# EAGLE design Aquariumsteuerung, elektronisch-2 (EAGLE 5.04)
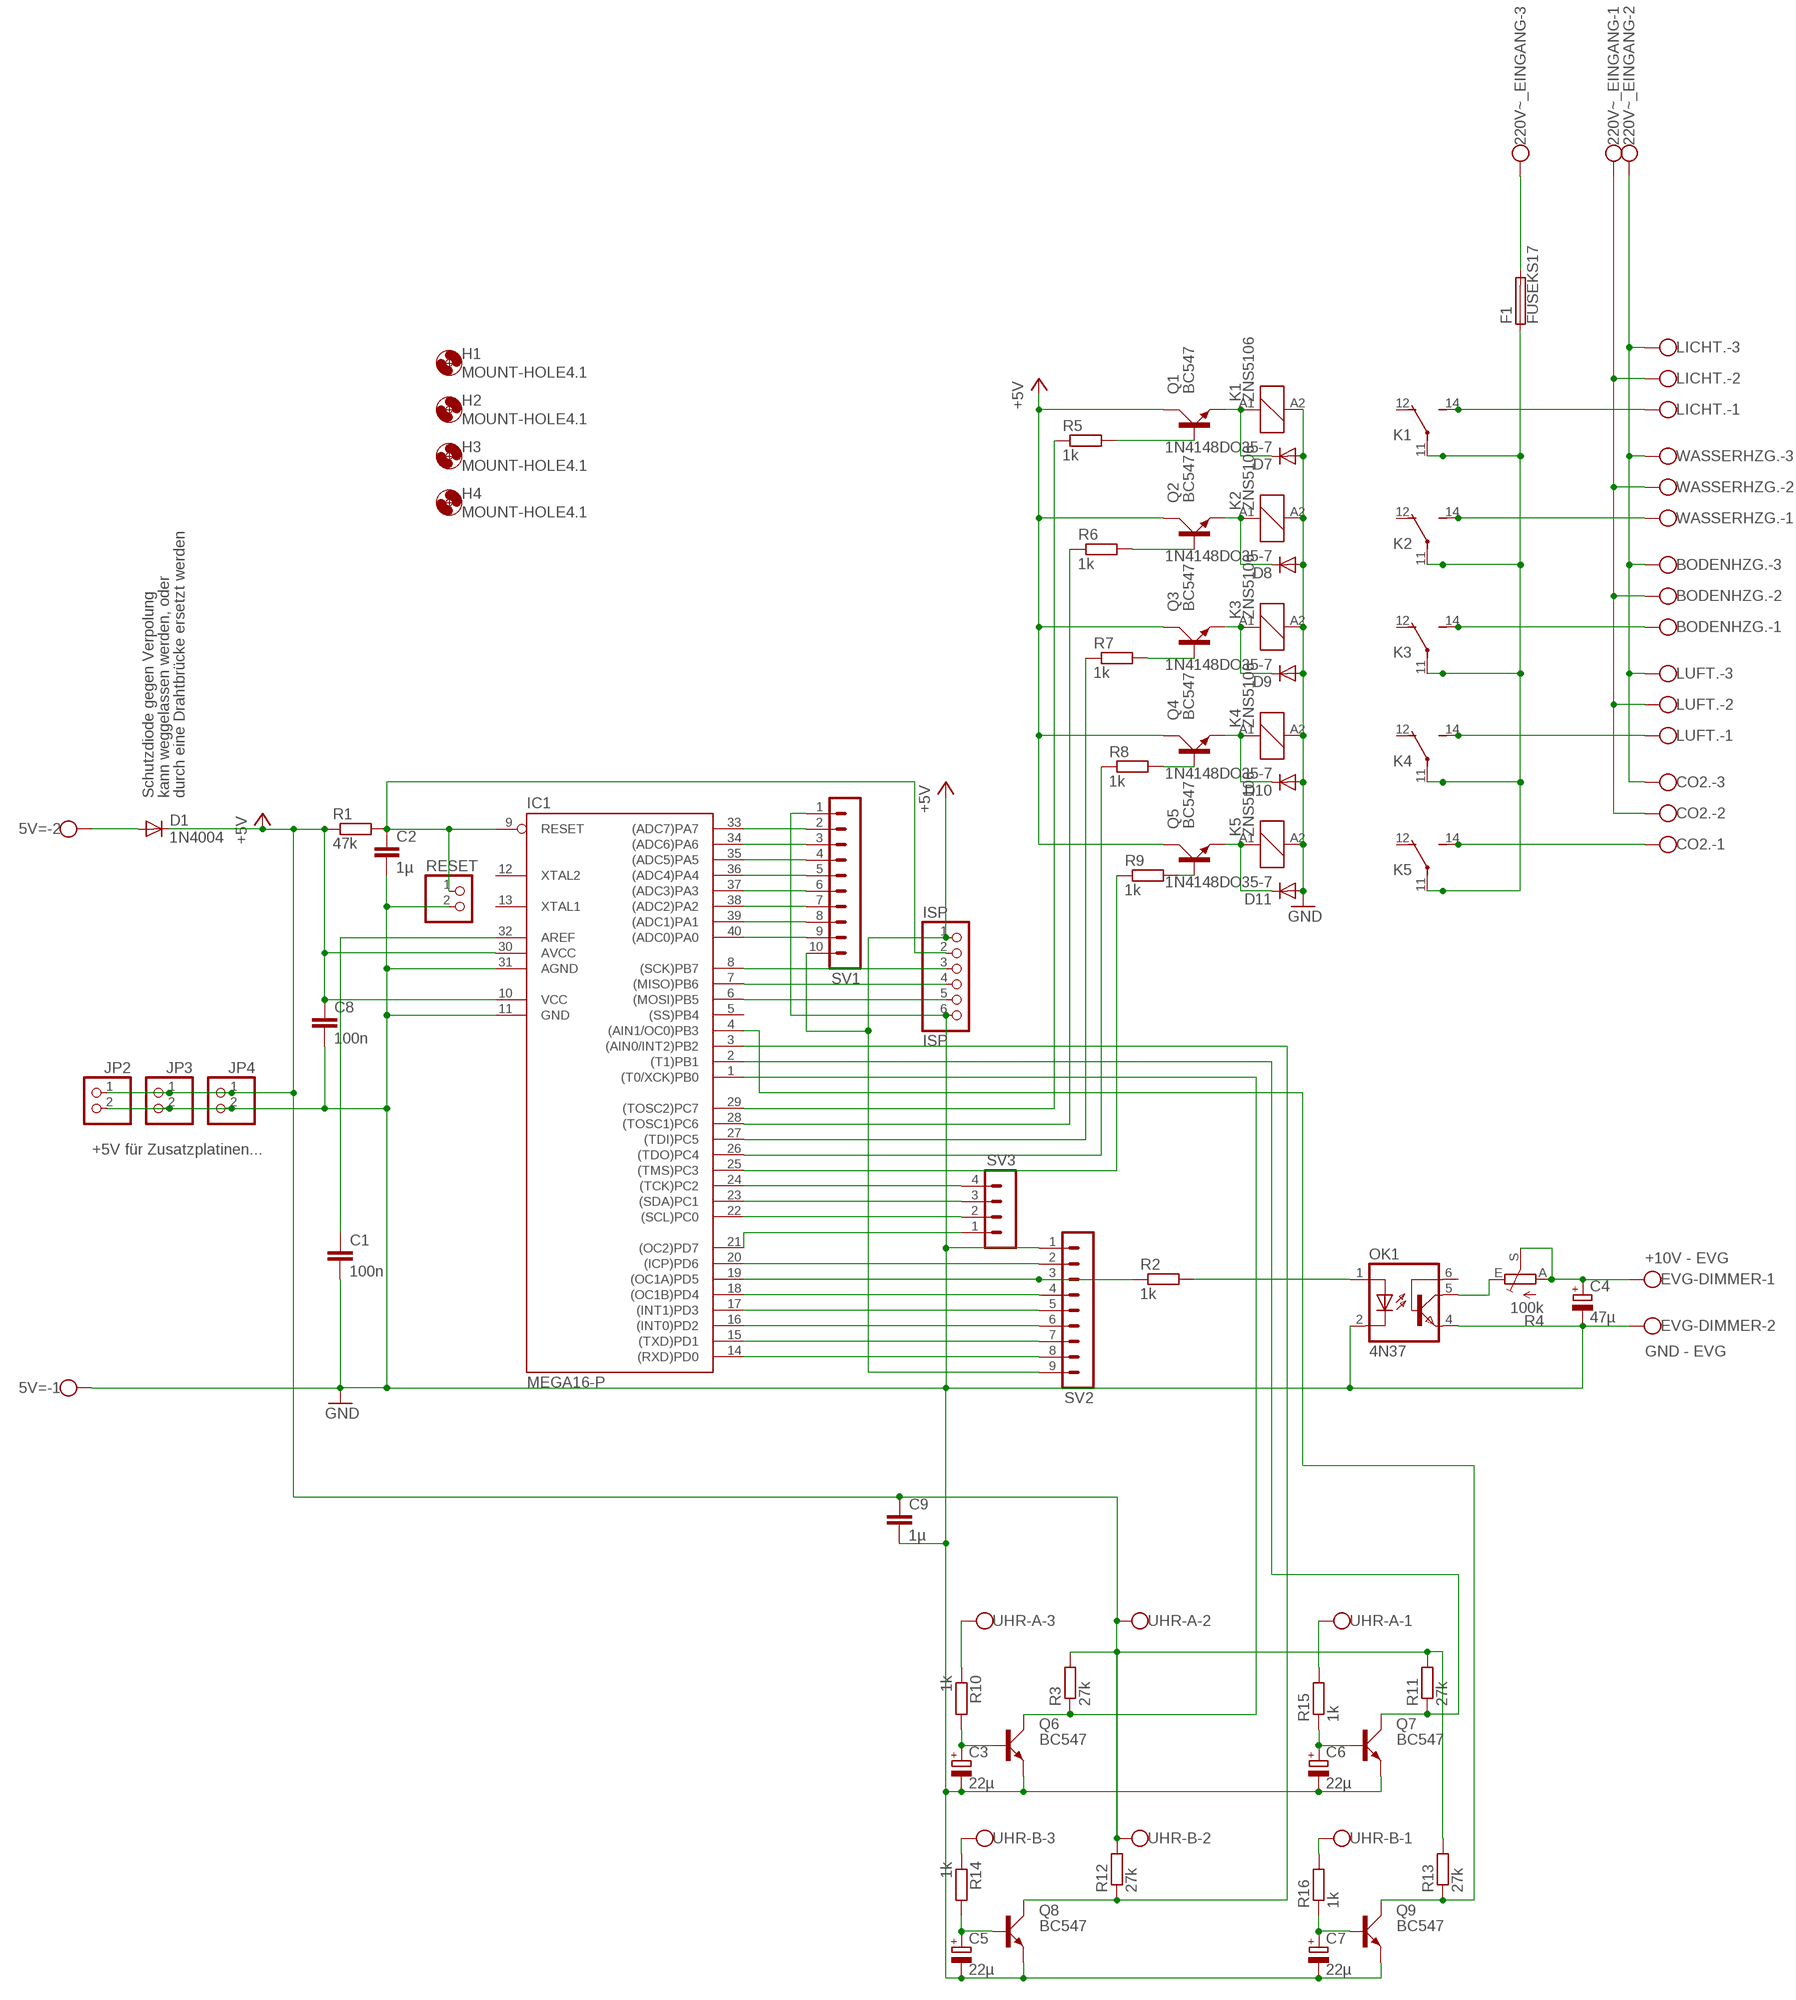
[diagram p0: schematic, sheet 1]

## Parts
5V=  W237-02P  [W237-132]
220V~_EINGANG  W237-03P  [W237-133]
BODENHZG.  W237-03P  [W237-133]
C1  100n  C-EU050-025X075  [C050-025X075]
C2  1µ  C-EU050-025X075  [C050-025X075]
C3  22µ  CPOL-EUE2.5-6  [E2,5-6]
C4  47µ  CPOL-EUE2.5-5  [E2,5-5]
C5  22µ  CPOL-EUE2.5-6  [E2,5-6]
C6  22µ  CPOL-EUE2.5-6  [E2,5-6]
C7  22µ  CPOL-EUE2.5-6  [E2,5-6]
C8  100n  C-EU050-025X075  [C050-025X075]
C9  1µ  C-EU050-025X075  [C050-025X075]
CO2.  W237-03P  [W237-133]
D1  1N4004  [DO41-10]
D7  1N4148DO35-7  [DO35-7]
D8  1N4148DO35-7  [DO35-7]
D9  1N4148DO35-7  [DO35-7]
D10  1N4148DO35-7  [DO35-7]
D11  1N4148DO35-7  [DO35-7]
EVG-DIMMER  W237-02P  [W237-132]
F1  FUSEKS17  [KS17]
H1  MOUNT-HOLE4.1  [4,1]
H2  MOUNT-HOLE4.1  [4,1]
H3  MOUNT-HOLE4.1  [4,1]
H4  MOUNT-HOLE4.1  [4,1]
IC1  MEGA16-P  [DIL40]
ISP  ISP  PINHD-1X6  [1X06]
JP2  PINHD-1X2  [1X02]
JP3  PINHD-1X2  [1X02]
JP4  PINHD-1X2  [1X02]
K1  ZNS5106  [ZN5]
K2  ZNS5106  [ZN5]
K3  ZNS5106  [ZN5]
K4  ZNS5106  [ZN5]
K5  ZNS5106  [ZN5]
LICHT.  W237-03P  [W237-133]
LUFT.  W237-03P  [W237-133]
OK1  4N37  [DIL06]
Q1  BC547  [SOT54A]
Q2  BC547  [SOT54A]
Q3  BC547  [SOT54A]
Q4  BC547  [SOT54A]
Q5  BC547  [SOT54A]
Q6  BC547  [SOT54A]
Q7  BC547  [SOT54A]
Q8  BC547  [SOT54A]
Q9  BC547  [SOT54A]
R1  47k  R-EU_0207/10  [0207/10]
R2  1k  R-EU_0207/10  [0207/10]
R3  27k  R-EU_0207/10  [0207/10]
R4  100k  TRIM_EU-S64W  [S64W]
R5  1k  R-EU_0207/10  [0207/10]
R6  1k  R-EU_0207/10  [0207/10]
R7  1k  R-EU_0207/10  [0207/10]
R8  1k  R-EU_0207/10  [0207/10]
R9  1k  R-EU_0207/10  [0207/10]
R10  1k  R-EU_0207/10  [0207/10]
R11  27k  R-EU_0207/10  [0207/10]
R12  27k  R-EU_0207/10  [0207/10]
R13  27k  R-EU_0207/10  [0207/10]
R14  1k  R-EU_0207/10  [0207/10]
R15  1k  R-EU_0207/10  [0207/10]
R16  1k  R-EU_0207/10  [0207/10]
RESET  PINHD-1X2  [1X02]
SV1  MA10-1  [MA10-1]
SV2  MA09-1  [MA09-1]
SV3  MA04-1  [MA04-1]
UHR-A  W237-03P  [W237-133]
UHR-B  W237-03P  [W237-133]
WASSERHZG.  W237-03P  [W237-133]

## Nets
+5V: C8.1 C9.1 D1.C IC1.10(VCC) IC1.30(AVCC) ISP.1 JP2.1 JP3.1 JP4.1 Q1.C Q2.C Q3.C Q4.C Q5.C R1.1 R3.2 R11.2 R12.2 R13.2 SV1.10 SV2.9 UHR-A.2 UHR-B.2
GND: 5V=.1 C1.2 C2.2 C3.- C4.- C5.- C6.- C7.- C8.2 C9.2 D7.A D8.A D9.A D10.A D11.A EVG-DIMMER.2 IC1.11(GND) IC1.31(AGND) ISP.6 JP2.2 JP3.2 JP4.2 K1.A2 K2.A2 K3.A2 K4.A2 K5.A2 OK1.2(C) OK1.4(EMI) Q6.E Q7.E Q8.E Q9.E RESET.2 SV1.1 SV2.1
L: F1.1 K1.11(2:P) K2.11(2:P) K3.11(2:P) K4.11(2:P) K5.11(2:P)
N: 220V~_EINGANG.1 BODENHZG..2 CO2..2 LICHT..2 LUFT..2 WASSERHZG..2
N$1: C3.+ Q6.B R10.2
N$2: C1.1 IC1.32(AREF)
N$3: IC1.19((OC1A)PD5) R2.1 SV2.3
N$4: K1.14(2:S) LICHT..1
N$5: K2.14(2:S) WASSERHZG..1
N$6: BODENHZG..1 K3.14(2:S)
N$7: K4.14(2:S) LUFT..1
N$8: CO2..1 K5.14(2:S)
N$9: D7.C K1.A1 Q1.E
N$10: D8.C K2.A1 Q2.E
N$11: 5V=.2 D1.A
N$12: IC1.8((SCK)PB7) ISP.3
N$13: D9.C K3.A1 Q3.E
N$14: D10.C K4.A1 Q4.E
N$15: OK1.1(A) R2.2
N$16: OK1.5(COL) R4.E
N$17: D11.C K5.A1 Q5.E
N$18: C4.+ EVG-DIMMER.1 R4.A R4.S
N$19: IC1.29((TOSC2)PC7) R5.1
N$20: IC1.28((TOSC1)PC6) R6.1
N$21: IC1.27((TDI)PC5) R7.1
N$22: IC1.26((TDO)PC4) R8.1
N$23: IC1.25((TMS)PC3) R9.1
N$24: IC1.7((MISO)PB6) ISP.4
N$25: IC1.6((MOSI)PB5) ISP.5
N$26: C2.1 IC1.9(RESET) ISP.2 R1.2 RESET.1
N$27: IC1.40((ADC0)PA0) SV1.9
N$28: IC1.39((ADC1)PA1) SV1.8
N$29: IC1.38((ADC2)PA2) SV1.7
N$30: IC1.24((TCK)PC2) SV3.4
N$31: IC1.23((SDA)PC1) SV3.3
N$32: IC1.22((SCL)PC0) SV3.2
N$33: IC1.37((ADC3)PA3) SV1.6
N$34: C7.+ Q9.B R16.1
N$35: IC1.2((T1)PB1) Q7.C R11.1
N$36: IC1.3((AIN0/INT2)PB2) Q8.C R12.1
N$37: IC1.4((AIN1/OC0)PB3) Q9.C R13.1
N$38: IC1.36((ADC4)PA4) SV1.5
N$39: R10.1 UHR-A.3
N$40: IC1.35((ADC5)PA5) SV1.4
N$41: IC1.34((ADC6)PA6) SV1.3
N$42: IC1.33((ADC7)PA7) SV1.2
N$43: IC1.1((T0/XCK)PB0) Q6.C R3.1
N$44: R14.1 UHR-B.3
N$45: C6.+ Q7.B R15.1
N$46: IC1.14((RXD)PD0) SV2.8
N$47: IC1.15((TXD)PD1) SV2.7
N$48: IC1.16((INT0)PD2) SV2.6
N$49: IC1.17((INT1)PD3) SV2.5
N$50: IC1.18((OC1B)PD4) SV2.4
N$51: IC1.20((ICP)PD6) SV2.2
N$52: IC1.21((OC2)PD7) SV3.1
N$53: C5.+ Q8.B R14.2
N$54: R16.2 UHR-B.1
N$55: R15.2 UHR-A.1
N$56: 220V~_EINGANG.3 F1.2
N$59: Q1.B R5.2
N$60: Q2.B R6.2
N$61: Q3.B R7.2
N$62: Q4.B R8.2
N$63: Q5.B R9.2
PE: 220V~_EINGANG.2 BODENHZG..3 CO2..3 LICHT..3 LUFT..3 WASSERHZG..3
Unconnected: IC1.5((SS)PB4) IC1.12(XTAL2) IC1.13(XTAL1) K1.12(2:O) K2.12(2:O) K3.12(2:O) K4.12(2:O) K5.12(2:O) OK1.6(BAS)

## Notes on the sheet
- Schutzdiode gegen Verpolung | kann weggelassen werden, oder | durch eine Drahtbrücke ersetzt werden
- +5V für Zusatzplatinen...
- +10V - EVG
- GND - EVG

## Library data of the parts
5V= EVG-DIMMER = Verbinder von Wago, Raster 5.08:W237-02P: WAGO SREW CLAMP
220V~_EINGANG BODENHZG. CO2. LICHT. LUFT. UHR-A UHR-B WASSERHZG. = Verbinder von Wago, Raster 5.08:W237-03P: WAGO SREW CLAMP
C1 C2 C8 C9 = Widerstände & Kondensatoren:C-EU: CAPACITOR, European symbol
C3-C7 = Widerstände & Kondensatoren:CPOL-EU: POLARIZED CAPACITOR, European symbol
D1 = Dioden:1N4004: DIODE
D7-D11 = diode:1N4148: DIODE
F1 = fuse:FUSE: Fuse
H1-H4 = Montagelöcher:MOUNT-HOLE: MOUNTING HOLE with drill center marker
IC1 = avr-4:MEGA16-P: MICROCONTROLLER 16 Kbytes FLASH 1 kbytes SRAM 512 bytes EEPROM USART 8-channel 10 bit ADC
ISP = Steckerleisten:PINHD-1X6: PIN HEADER
JP2-JP4 RESET = Steckerleisten:PINHD-1X2: PIN HEADER
K1-K5 = relay:ZNS5*: Miniature Power PCB Relay SCHRACK 1pole 10 A Source: http://www.schrack.com/.. 5847.pdf
OK1 = Optokoppler:4N37: MOTOROLA OPTO COUPLER
Q1-Q9 = Transistor-Kleinsignal:BC547: NPN TRANSISTOR
R1-R3 R5-R16 = Widerstände & Kondensatoren:R-EU_: RESISTOR, European symbol
R4 = Poti's:TRIM_EU-: POTENTIOMETER
SV1 = Steckerleisten, männlich:MA10-1: PIN HEADER
SV2 = Steckerleisten, männlich:MA09-1: PIN HEADER
SV3 = Steckerleisten, männlich:MA04-1: PIN HEADER

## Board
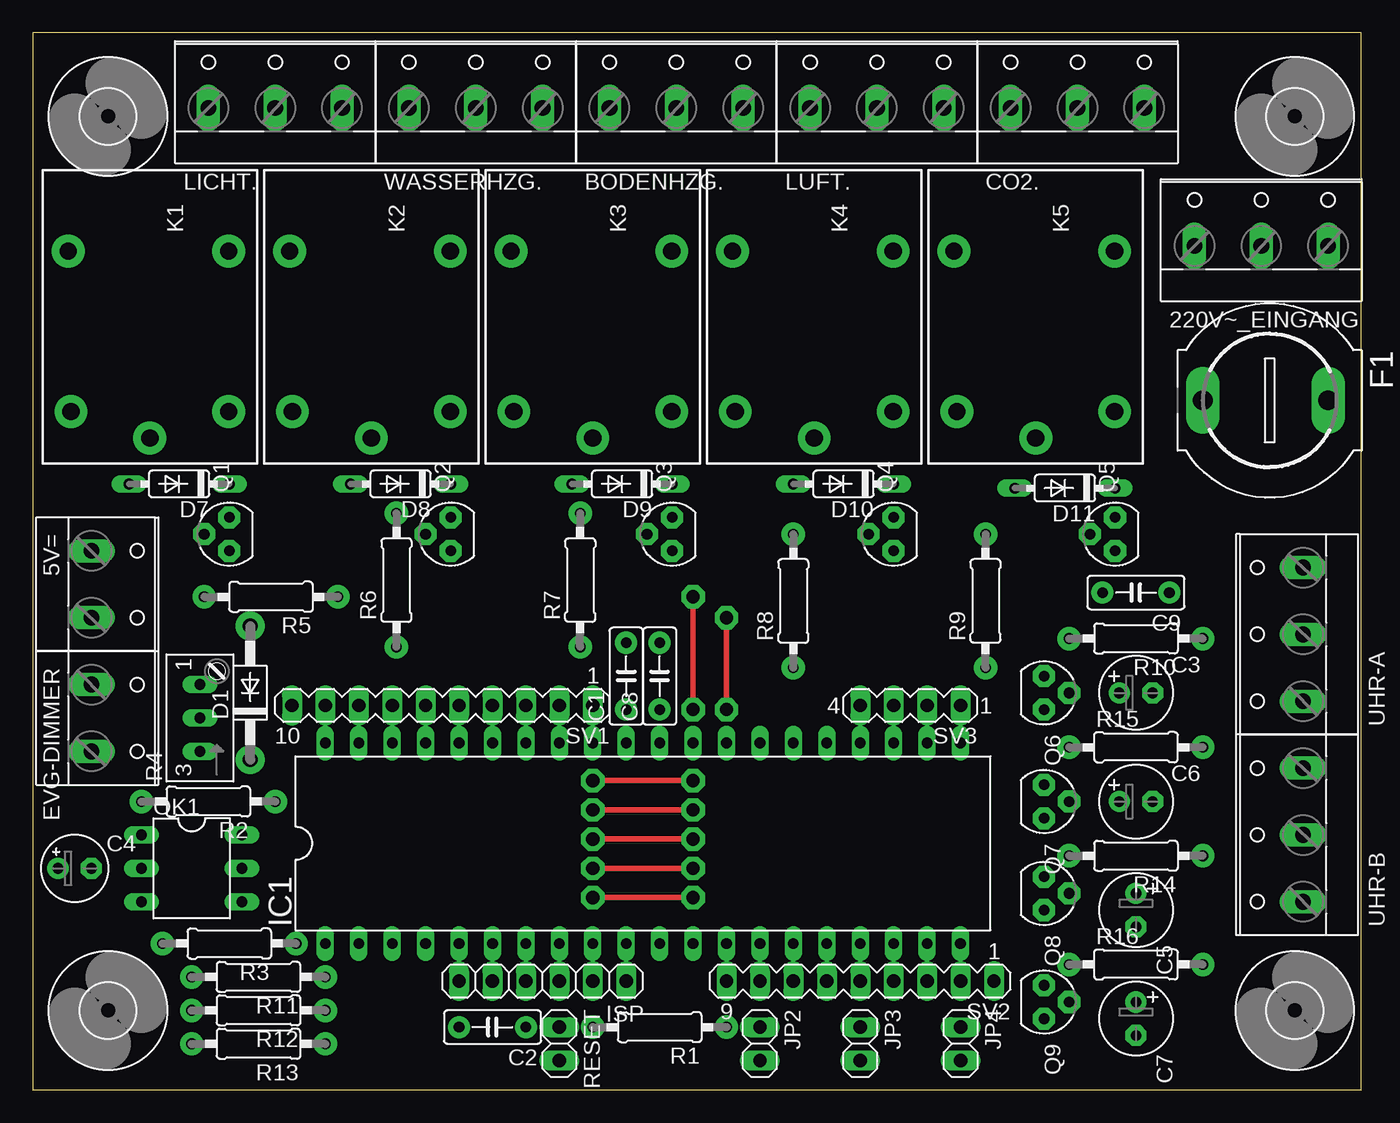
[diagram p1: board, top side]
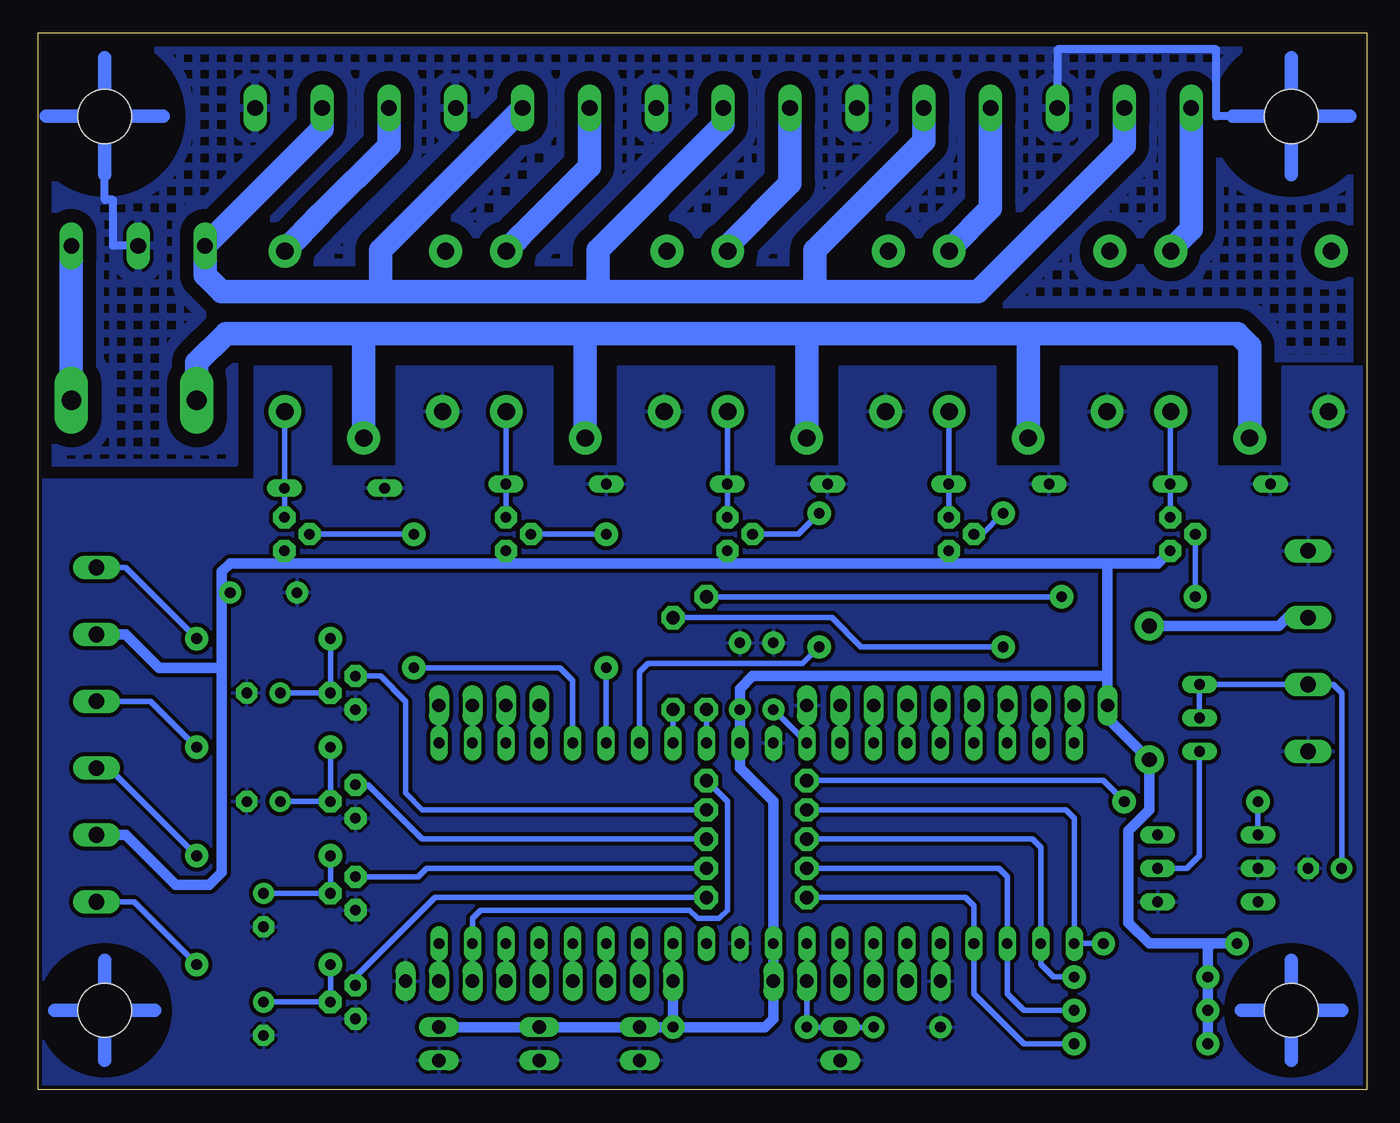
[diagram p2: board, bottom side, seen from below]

Size 100.95 x 80.32 mm. Coordinates in mm from the lower left corner, seen from the top.
Outline: 0,0 100.95,0 100.95,80.32 0,80.32 0,0
Copper layers (1*16): Top 0.035mm / dielectric 1.5mm / Bottom 0.035mm
Design rules "default": minimum track width 10mil, minimum drill 24mil, track to track 12mil, track to pad 12mil, pad to pad 12mil, via to via 12mil, smd to smd 12mil, copper to edge 12mil, drill to drill 12mil, minimum pad ring 10mil, minimum via ring 10mil, stop-mask expansion 4mil, vias tented up to drill 0mil, thermal gap 10mil

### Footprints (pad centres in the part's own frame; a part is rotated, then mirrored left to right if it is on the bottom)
W237-132 = drill 1.194 long: 1 -2.54,-0.635; 2 2.54,-0.635
W237-133 = drill 1.194 long: 1 -5.08,-0.635; 2 0,-0.635; 3 5.08,-0.635
C050-025X075 = drill 0.813 pad 1.676 round: 1 -2.54,0; 2 2.54,0
E2,5-6 = drill 0.813 pad 1.6 round: + -1.27,0 | drill 0.813 pad 1.6 octagon: - 1.27,0
E2,5-5 = drill 0.813 pad 1.6 round: + -1.27,0 | drill 0.813 pad 1.6 octagon: - 1.27,0
DO41-10 = drill 1.118 pad 2.184 round: A 5.08,0; C -5.08,0
DO35-7 = drill 0.813 long: A 3.81,0; C -3.81,0
KS17 = drill 1.499 pad 2.54 long: 1 0,-5.08; 2 0,4.445
4,1 = hole 4.1: 0,0
DIL40 = drill 0.813 long: 1 -24.13,-7.62; 2 -21.59,-7.62; 3 -19.05,-7.62; 4 -16.51,-7.62; 5 -13.97,-7.62; 6 -11.43,-7.62; 7 -8.89,-7.62; 8 -6.35,-7.62; 9 -3.81,-7.62; 10 -1.27,-7.62; 11 1.27,-7.62; 12 3.81,-7.62; 13 6.35,-7.62; 14 8.89,-7.62; 15 11.43,-7.62; 16 13.97,-7.62; 17 16.51,-7.62; 18 19.05,-7.62; 19 21.59,-7.62; 20 24.13,-7.62; 21 24.13,7.62; 22 21.59,7.62; 23 19.05,7.62; 24 16.51,7.62; 25 13.97,7.62; 26 11.43,7.62; 27 8.89,7.62; 28 6.35,7.62; 29 3.81,7.62; 30 1.27,7.62; 31 -1.27,7.62; 32 -3.81,7.62; 33 -6.35,7.62; 34 -8.89,7.62; 35 -11.43,7.62; 36 -13.97,7.62; 37 -16.51,7.62; 38 -19.05,7.62; 39 -21.59,7.62; 40 -24.13,7.62
1X06 = drill 1.016 long: 1 -6.35,0; 2 -3.81,0; 3 -1.27,0; 4 1.27,0; 5 3.81,0; 6 6.35,0
1X02 = drill 1.016 long: 1 -1.27,0; 2 1.27,0
ZN5 = drill 1.3 pad 2.5 round: 11 8.89,0; 12 -5.31,-6.2; 14 -5.31,6; A1 6.89,6; A2 6.89,-6
DIL06 = drill 0.813 long: 1 -2.54,-3.81; 2 0,-3.81; 3 2.54,-3.81; 4 2.54,3.81; 5 0,3.81; 6 -2.54,3.81
SOT54A = drill 0.813 pad 1.676 octagon: B 0,1.905; C -1.27,0; E 1.27,0
0207/10 = drill 0.813 pad 1.778 round: 1 -5.08,0; 2 5.08,0
S64W = drill 0.813 long: A 2.54,1.27; E -2.54,1.27; S 0,1.27
MA10-1 = drill 1.016 long: 1 -11.43,0; 2 -8.89,0; 3 -6.35,0; 4 -3.81,0; 5 -1.27,0; 6 1.27,0; 7 3.81,0; 8 6.35,0; 9 8.89,0; 10 11.43,0
MA09-1 = drill 1.016 long: 1 -10.16,0; 2 -7.62,0; 3 -5.08,0; 4 -2.54,0; 5 0,0; 6 2.54,0; 7 5.08,0; 8 7.62,0; 9 10.16,0
MA04-1 = drill 1.016 long: 1 -3.81,0; 2 -1.27,0; 3 1.27,0; 4 3.81,0

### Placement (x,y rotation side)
5V=  5.08,38.42 270 top
220V~_EINGANG  93.34,64.77 0 top
BODENHZG.  48.9,75.25 0 top
C1  45.09,31.43 90 top
C2  34.92,4.76 180 top
C3  83.82,30.16 0 top
C4  3.17,16.83 0 top
C5  83.82,13.65 270 top
C6  83.82,21.91 0 top
C7  83.82,5.4 270 top
C8  47.62,31.43 90 top
C9  83.82,37.78 180 top
CO2.  79.38,75.25 0 top
D1  16.51,30.16 90 top
D7  11.11,46.04 180 top
D8  27.94,46.04 180 top
D9  44.77,46.04 180 top
D10  61.59,46.04 180 top
D11  78.42,45.72 180 top
EVG-DIMMER  5.08,28.26 270 top
F1  93.98,52.39 270 top
H1  5.71,73.98 0 top
H2  95.89,73.98 0 top
H3  5.71,6.03 0 top
H4  95.89,6.03 0 top
IC1  46.35,18.73 0 top
ISP  38.73,8.26 180 top
JP2  55.24,3.49 270 top
JP3  62.87,3.49 270 top
JP4  70.48,3.49 270 top
K1  8.89,58.42 270 top
K2  25.72,58.42 270 top
K3  42.55,58.42 270 top
K4  59.37,58.42 270 top
K5  76.2,58.42 270 top
LICHT.  18.41,75.25 0 top
LUFT.  64.14,75.25 0 top
OK1  12.06,16.83 270 top
Q1  14.92,42.23 90 top
Q2  31.75,42.23 90 top
Q3  48.58,42.23 90 top
Q4  65.41,42.23 90 top
Q5  82.23,42.23 90 top
Q6  76.83,30.16 270 top
Q7  76.83,21.91 270 top
Q8  76.83,14.92 270 top
Q9  76.83,6.67 270 top
R1  47.62,4.76 180 top
R2  13.34,21.91 180 top
R3  14.92,11.11 180 top
R4  13.97,28.26 90 top
R5  18.1,37.47 180 top
R6  27.62,38.73 90 top
R7  41.59,38.73 90 top
R8  57.78,37.15 90 top
R9  72.39,37.15 90 top
R10  83.82,34.29 180 top
R11  17.14,8.57 180 top
R12  17.14,6.03 180 top
R13  17.14,3.49 180 top
R14  83.82,17.78 180 top
R15  83.82,26.04 0 top
R16  83.82,9.53 0 top
RESET  40.01,3.49 270 top
SV1  31.11,29.21 180 top
SV2  62.87,8.26 180 top
SV3  66.67,29.21 180 top
UHR-A  95.89,34.61 90 top
UHR-B  95.89,19.37 90 top
WASSERHZG.  33.66,75.25 0 top

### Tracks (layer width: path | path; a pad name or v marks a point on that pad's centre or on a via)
+5V
  Bottom 0.813: R1.1 45.72,4.76 45.09,5.4 ISP.1 IC1.10 45.09,21.91 47.62,24.45 IC1.30 C8.1 47.62,30.48 46.67,31.43 19.68,31.43 | R1.1 JP2.1 JP3.1 JP4.1 | 11.75,11.11 R3.2 | 11.75,11.11 16.51,11.11 18.1,12.7 18.1,19.68 16.51,21.27 D1.C 19.68,28.26 SV1.10 19.68,31.43 | R13.2 R12.2 R11.2 12.06,10.79 11.75,11.11 | R1.1 SV2.9 | UHR-B.2 94.3,19.37 90.49,15.56 87.95,15.56 87,16.51 87,32.07 | 87,37.78 87,32.07 | UHR-A.2 94.3,34.61 91.76,32.07 87,32.07 | 87,37.78 C9.1 | Q1.C 15.88,40.01 19.68,40.01 | 31.75,40.01 Q2.C | 19.68,40.01 31.75,40.01 | 48.58,40.01 Q3.C | 31.75,40.01 48.58,40.01 | 65.41,40.01 Q4.C | 48.58,40.01 65.41,40.01 | 82.23,40.01 Q5.C | 65.41,40.01 82.23,40.01 | 82.23,40.01 86.36,40.01 87,39.37 87,37.78 | 19.68,31.43 19.68,40.01
GND
  pour Bottom: 0,0 100.97,0 100.97,46.36 84.45,46.36 84.45,54.93 78.74,54.93 78.74,47.31 73.66,47.31 73.66,54.93 61.91,54.93 61.91,47.31 56.83,47.31 56.83,54.93 45.09,54.93 45.09,47.31 40.01,47.31 40.01,54.93 28.26,54.93 28.26,47.31 23.18,47.31 23.18,54.93 11.43,54.93 11.43,47.31 6.35,47.31 6.35,54.93 0,54.93
L
  Bottom 1.778: F1.1 88.9,55.25 86.68,57.47 76.2,57.47 | 25.72,57.47 9.84,57.47 8.89,56.51 K1.11 | 25.72,57.47 42.55,57.47 | 42.55,57.47 59.69,57.47 | 59.69,57.47 76.2,57.47 | 25.72,57.47 K2.11 | 42.55,57.47 K3.11 | K4.11 59.37,57.15 59.69,57.47 | 76.2,57.47 K5.11
N
  Bottom 1.778: LICHT..2 18.41,71.76 29.53,60.64 41.91,60.64 | 41.91,60.64 58.42,60.64 | 58.42,60.64 74.93,60.64 | WASSERHZG..2 33.66,72.07 41.91,63.82 41.91,60.64 | BODENHZG..2 48.9,73.34 58.42,63.82 58.42,60.64 | CO2..2 79.38,73.02 220V~_EINGANG.1 88.27,61.91 87,60.64 74.93,60.64 | LUFT..2 74.93,63.82 74.93,60.64
N$1
  Bottom 0.406: R10.2 Q6.B C3.+
N$2
  Bottom 0.406: IC1.32 C1.1
N$3  (via drill 1 pad 1.78)
  Top 0.406: v42.55,23.49 v50.16,23.49
  Bottom 0.406: v50.16,23.49 48.58,21.91 48.58,13.65 49.21,13.02 50.8,13.02 51.44,13.65 67.31,13.65 67.94,13.02 IC1.19 SV2.3 | v42.55,23.49 20,23.49 R2.1
N$4
  Bottom 1.778: K1.14 14.89,63.85 13.34,65.41 LICHT..1
N$5
  Bottom 1.778: K2.14 31.72,63.85 28.57,66.99 WASSERHZG..1
N$6
  Bottom 1.778: K3.14 48.55,64.17 43.81,68.9 BODENHZG..1
N$7
  Bottom 1.778: K4.14 64.22,65 59.05,70.17 LUFT..1
N$8
  Bottom 1.778: K5.14 79.46,66.59 74.3,71.76 CO2..1
N$9
  Bottom 0.406: Q1.E D7.C 14.92,51.5 K1.A1
N$10
  Bottom 0.406: Q2.E D8.C 31.75,51.5 K2.A1
N$11
  Bottom 0.813: 5V=.2 6.03,35.88 6.67,35.24 D1.A
N$12
  Bottom 0.406: ISP.3 IC1.8
N$13
  Bottom 0.406: Q3.E D9.C 48.58,51.5 K3.A1
N$14
  Bottom 0.406: Q4.E D10.C 65.41,51.5 K4.A1
N$15
  Bottom 0.406: OK1.1 R2.2
N$16
  Bottom 0.406: R4.E 12.7,17.78 13.65,16.83 OK1.5
N$17
  Bottom 0.406: Q5.E D11.C 82.23,51.5 K5.A1
N$18
  Bottom 0.406: C4.+ 1.91,30.16 2.54,30.8 EVG-DIMMER.1 R4.A R4.S
N$19  (via drill 1 pad 1.78)
  Top 0.406: v50.16,37.47 v50.16,28.89
  Bottom 0.406: v50.16,28.89 IC1.29 | R5.1 v50.16,37.47
N$20  (via drill 1 pad 1.78)
  Top 0.406: v52.7,35.88 v52.7,28.89
  Bottom 0.406: R6.1 38.42,33.65 40.64,35.88 v52.7,35.88 | v52.7,28.89 IC1.28
N$21
  Bottom 0.406: R7.1 42.86,32.39 54.61,32.39 55.24,31.75 IC1.27
N$22
  Bottom 0.406: IC1.26 R8.1
N$23
  Bottom 0.406: R9.1 61.28,32.07 60.33,31.11 IC1.25
N$24
  Bottom 0.406: ISP.4 IC1.7
N$25
  Bottom 0.406: ISP.5 IC1.6
N$26
  Bottom 0.406: IC1.9 ISP.2 R1.2 RESET.1 C2.1
N$27
  Bottom 0.406: IC1.40 SV1.9
N$28
  Bottom 0.406: IC1.39 SV1.8
N$29
  Bottom 0.406: IC1.38 SV1.7
N$30
  Bottom 0.406: IC1.24 SV3.4
N$31
  Bottom 0.406: IC1.23 SV3.3
N$32
  Bottom 0.406: IC1.22 SV3.2
N$33
  Bottom 0.406: 29.84,26.99 IC1.37 SV1.6
N$34
  Bottom 0.406: R16.1 Q9.B C7.+
N$35  (via drill 1 pad 1.78)
  Top 0.406: v42.55,19.05 v50.16,19.05
  Bottom 0.406: v42.55,19.05 25.4,19.05 24.77,18.42 IC1.2 24.77,9.52 23.81,8.57 R11.1 | v50.16,19.05 71.75,19.05 75.88,23.18 Q7.C
N$36  (via drill 1 pad 1.78)
  Top 0.406: v42.55,16.83 v50.16,16.83
  Bottom 0.406: v50.16,16.83 71.44,16.83 72.07,16.19 Q8.C | v42.55,16.83 27.94,16.83 27.3,16.19 IC1.3 27.3,7.3 26.04,6.03 R12.1
N$37  (via drill 1 pad 1.78)
  Top 0.406: v42.55,14.6 v50.16,14.6
  Bottom 0.406: v42.55,14.6 30.48,14.6 29.84,13.97 IC1.4 29.84,7.3 26.04,3.49 R13.1 | v50.16,14.6 70.8,14.6 76.83,8.57 Q9.C
N$38
  Bottom 0.406: IC1.36 SV1.5
N$39
  Bottom 0.406: R10.1 94.3,39.69 UHR-A.3
N$40
  Bottom 0.406: IC1.35 SV1.4
N$41
  Bottom 0.406: IC1.34 SV1.3
N$42
  Bottom 0.406: IC1.33 SV1.2
N$43  (via drill 1 pad 1.78)
  Top 0.406: v42.55,21.27 v50.16,21.27
  Bottom 0.406: v42.55,21.27 22.86,21.27 22.23,20.64 IC1.1 R3.1 | v50.16,21.27 71.75,21.27 73.03,22.54 73.03,29.53 74.93,31.43 Q6.C
N$44
  Bottom 0.406: R14.1 95.57,24.45 UHR-B.3
N$45
  Bottom 0.406: R15.1 Q7.B C6.+
N$46
  Bottom 0.406: SV2.8 IC1.14
N$47
  Bottom 0.406: SV2.7 IC1.15
N$48
  Bottom 0.406: SV2.6 IC1.16
N$49
  Bottom 0.406: SV2.5 IC1.17
N$50
  Bottom 0.406: SV2.4 IC1.18
N$51
  Bottom 0.406: SV2.2 IC1.20
N$52
  Bottom 0.406: IC1.21 SV3.1
N$53
  Bottom 0.406: R14.2 Q8.B C5.+
N$54
  Bottom 0.406: R16.2 93.66,14.29 UHR-B.1
N$55
  Bottom 0.406: R15.2 92.39,29.53 UHR-A.1
N$56
  Bottom 1.778: F1.2 220V~_EINGANG.3
N$59
  Bottom 0.406: R5.2 Q1.B
N$60
  Bottom 0.406: Q2.B 29.21,42.23 R6.2
N$61
  Bottom 0.406: Q3.B 43.18,42.23 R7.2
N$62
  Bottom 0.406: R8.2 Q4.B
N$63
  Bottom 0.406: R9.2 Q5.B
N$64
  pour Bottom: 44.13,23.49 20,23.49 20,1.9 44.13,1.9
N$65
  Bottom 1.016: 4.45,6.03 1.91,6.03 | 4.45,6.03 5.71,7.3 | 5.71,7.3 5.71,9.84 | 6.99,6.03 5.71,7.3 | 6.99,6.03 9.53,6.03 | 5.71,4.76 6.99,6.03 | 5.71,2.22 5.71,4.76 | 5.71,4.76 4.45,6.03
N$66
  Bottom 1.016: 94.61,6.03 92.08,6.03 | 94.61,6.03 95.89,7.3 | 95.89,7.3 95.89,9.84 | 97.16,6.03 95.89,7.3 | 97.16,6.03 99.69,6.03 | 95.89,4.76 97.16,6.03 | 95.89,2.22 95.89,4.76 | 95.89,4.76 94.61,6.03
PE
  Bottom 0.61: LICHT..3 23.5,79.06 11.43,79.06 11.43,73.98 10.16,73.98 | 220V~_EINGANG.2 95.25,64.14 95.25,67.63 95.89,67.63 95.89,69.53
  Bottom 1.016: 6.99,73.98 10.16,73.98 | 6.99,73.98 5.71,75.25 | 5.71,75.25 5.71,78.42 | 4.45,73.98 5.71,75.25 | 4.45,73.98 1.27,73.98 | 5.71,72.71 4.45,73.98 | 5.71,69.53 5.71,72.71 | 5.71,72.71 6.99,73.98 | 95.89,75.25 95.89,78.42 | 94.61,73.98 95.89,75.25 | 94.61,73.98 91.44,73.98 | 95.89,72.71 94.61,73.98 | 95.89,69.53 95.89,72.71 | 95.89,72.71 97.16,73.98 | 97.16,73.98 100.33,73.98 | 97.16,73.98 95.89,75.25
  pour Bottom (isolate 1.016, hatched): 0,80.33 0,55.56 6.99,55.56 6.99,47.62 10.79,47.62 10.79,55.56 23.81,55.56 23.81,47.62 27.62,47.62 27.62,55.56 40.64,55.56 40.64,47.62 44.45,47.62 44.45,55.56 57.47,55.56 57.47,47.62 61.28,47.62 61.28,55.56 74.3,55.56 74.3,47.62 78.11,47.62 78.11,55.56 86.04,55.56 86.04,47.62 100.97,47.62 100.97,80.33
